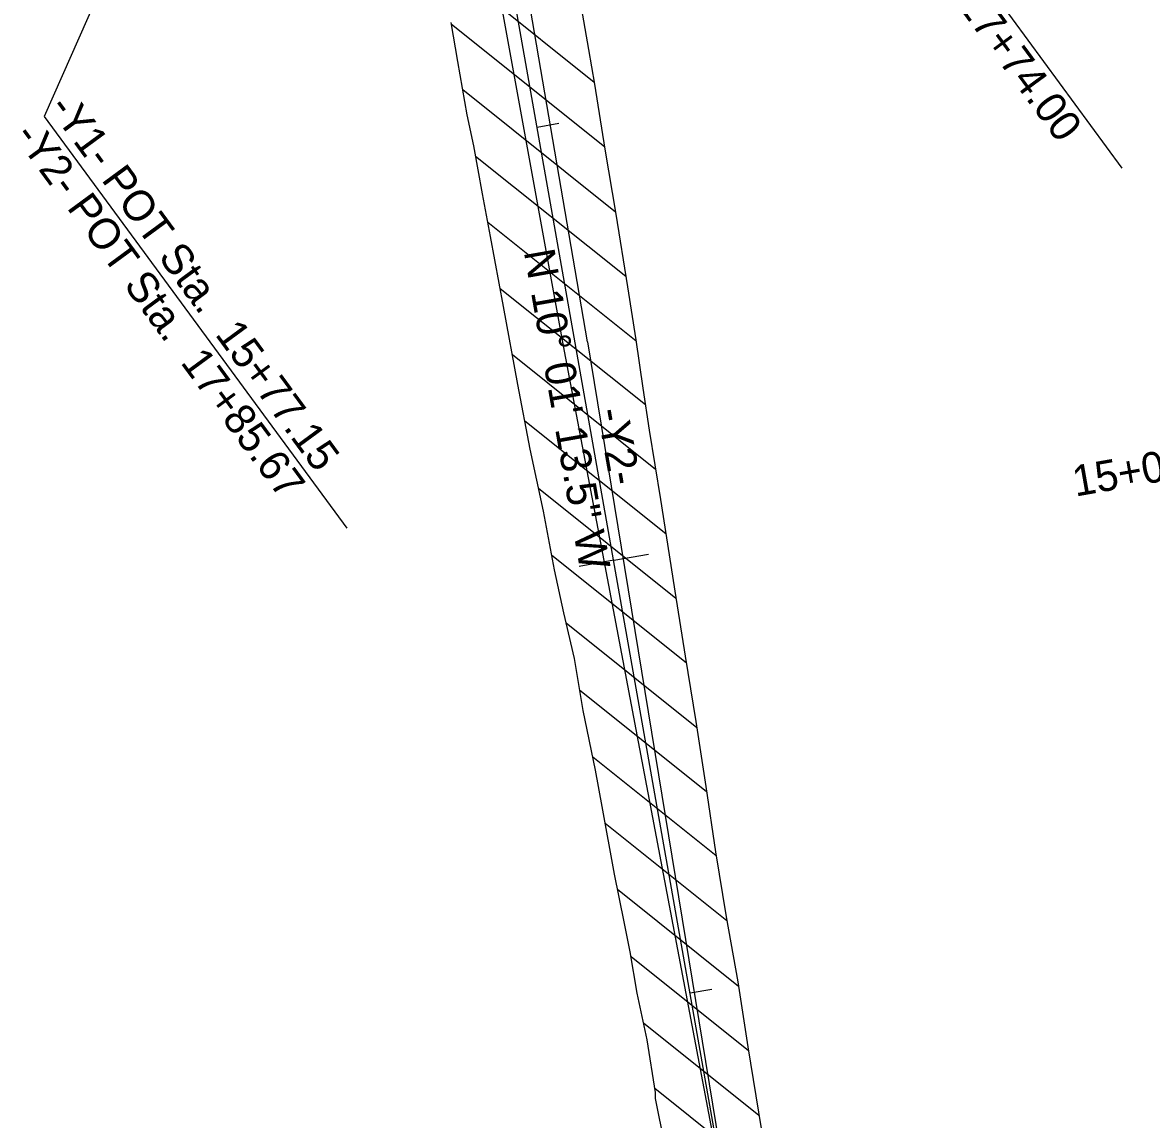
# Model space of a CAD drawing. Extents: x 1762196 to 1766326, y 709922 to 713142.
# Drawn here: x 1763778.9 to 1764035.8, y 712001.2 to 712250.7 of the extents above; entities that cross this region are included whole.
import ezdxf

# ---------------------------------------------------------------- set-up
doc = ezdxf.new("R2010")
doc.units = 0
for name, color, linetype in [('Old_Level_40', 7, 'Continuous'), ('Prop Horizontal Alignment', 7, 'Continuous'), ('Prop Horizontal Alignment Direction Label', 7, 'Continuous'), ('Prop Horizontal Alignment Station Label', 7, 'Continuous'), ('Prop Horizontal Alignment Tick Label', 7, 'Continuous'), ('Prop Horizontal Alignment Tick Large', 7, 'Continuous'), ('Prop Horizontal Alignment Tick Small', 7, 'Continuous'), ('Prop Lane Lines', 7, 'Continuous')]:
    doc.layers.add(name, color=color, linetype=linetype)

msp = doc.modelspace()

# ---------------------------------------------------------------- linework, layer by layer
at = {"layer": 'Old_Level_40'}
for p, q in [((1763873.32, 712265.77), (1763908.97, 712237.21)), ((1763876.51, 712250.39), (1763911.28, 712222.56)), ((1763879.05, 712235.55), (1763913.83, 712207.7)), ((1763881.98, 712220.39), (1763916.14, 712193.04)), ((1763884.77, 712205.35), (1763918.5, 712178.34)), ((1763887.57, 712190.29), (1763920.61, 712163.84)), ((1763890.36, 712175.25), (1763922.92, 712149.18)), ((1763893.17, 712160.19), (1763925.25, 712134.5)), ((1763896.3, 712144.87), (1763927.56, 712119.84)), ((1763899.34, 712129.63), (1763929.89, 712105.16)), ((1763902.6, 712114.2), (1763932.3, 712090.42)), ((1763905.65, 712098.95), (1763934.54, 712075.82)), ((1763908.63, 712083.75), (1763936.73, 712061.25)), ((1763911.47, 712068.67), (1763939.12, 712046.53)), ((1763914.29, 712053.6), (1763941.79, 712031.58)), ((1763917.36, 712038.33), (1763944.08, 712016.94)), ((1763920.19, 712023.25), (1763946.46, 712002.22)), ((1763943.94, 712017.75), (1763953.64, 711957.83)), ((1763922.76, 712008.38), (1763948.84, 711987.5)), ((1763933.12, 711954.2), (1763922.95, 712006.03))]:
    msp.add_line(p, q, dxfattribs=at)
for points in [[(1763889.06, 712351.06), (1763889.2, 712350.17), (1763891.58, 712335.89), (1763894.16, 712321.04), (1763896.99, 712306.32), (1763899.39, 712291.51), (1763902, 712276.76), (1763904.54, 712261.98), (1763905.99, 712254.16), (1763907.71, 712244.63)], [(1763922.95, 712006.03), (1763922.92, 712007.35), (1763921.05, 712019.33), (1763918.73, 712029.93), (1763917.19, 712039.39), (1763915.76, 712046.18), (1763913.6, 712057.05), (1763910.79, 712072.4), (1763909.28, 712080.67), (1763906.43, 712094.25), (1763904.46, 712106.07), (1763902.08, 712116.51), (1763899.97, 712126.28), (1763897.44, 712139.59), (1763894.39, 712153.71), (1763891.62, 712168.43), (1763888.34, 712186.16), (1763885.38, 712202.09), (1763883.55, 712211.79), (1763881.56, 712222.74), (1763880.08, 712229.74), (1763877.93, 712241.89), (1763876.45, 712250.78)], [(1763907.71, 712244.63), (1763909.05, 712236.75), (1763911.37, 712221.97), (1763913.91, 712207.19), (1763916.52, 712190.64)], [(1763916.52, 712190.64), (1763918.47, 712178.59), (1763920.04, 712167.57), (1763921.49, 712158.06), (1763924.02, 712142.29), (1763926.41, 712127.21)], [(1763926.41, 712127.21), (1763927.31, 712121.41), (1763929.65, 712106.6), (1763932.09, 712091.79), (1763934.37, 712076.97), (1763936.59, 712062.14), (1763938.97, 712047.35), (1763941.63, 712032.57), (1763943.94, 712017.75)]]:
    msp.add_lwpolyline(points, dxfattribs=at)
at = {"layer": 'Prop Horizontal Alignment'}
msp.add_line((1763966.92, 711825.6), (1763863.71, 712409.75), dxfattribs=at)
at = {"layer": 'Prop Horizontal Alignment Station Label'}
for p, q in [((1763863.71, 712409.75), (1763783.81, 712229.41)), ((1763959.83, 712311.81), (1764029.03, 712217.65)), ((1763783.81, 712229.41), (1763852.68, 712135.7))]:
    msp.add_line(p, q, dxfattribs=at)
at = {"layer": 'Prop Horizontal Alignment Tick Large'}
for q in [(1763921.29, 712129.83), (1763905.54, 712127.04)]:
    msp.add_line((1763913.41, 712128.43), q, dxfattribs=at)
at = {"layer": 'Prop Horizontal Alignment Tick Small'}
for p, q in [((1763900.94, 712227.78), (1763896.01, 712226.91)), ((1763935.74, 712030.83), (1763930.81, 712029.96))]:
    msp.add_line(p, q, dxfattribs=at)
at = {"layer": 'Prop Lane Lines'}
for p, q in [((1763902.01, 712177.19), (1763874.85, 712326.52)), ((1763907.42, 712178.15), (1763882.06, 712325.99)), ((1763943.86, 711956.1), (1763902.01, 712177.19)), ((1763907.42, 712178.15), (1763943.86, 711956.1))]:
    msp.add_line(p, q, dxfattribs=at)

# ---------------------------------------------------------------- texts
at = {"layer": 'Prop Horizontal Alignment Direction Label'}
for s, rotation, p in [('N 10%%d 01\' 13.5" W', 280.0204, (1763892.94, 712198.63)), ('-Y2-', 280.0243, (1763909.61, 712162.54))]:
    msp.add_text(s, height=7, rotation=rotation, dxfattribs=at).set_placement(p)
at = {"layer": 'Prop Horizontal Alignment Station Label'}
for s, p in [('-Y2- POT Sta.  17+74.00', (1763953.58, 712306.29)), ('-Y1- POT Sta.  15+77.15', (1763784.66, 712231.34)), ('-Y2- POT Sta.  17+85.67', (1763776.8, 712224.97))]:
    msp.add_text(s, height=7, rotation=306.3131, dxfattribs=at).set_placement(p)
at = {"layer": 'Prop Horizontal Alignment Tick Label'}
msp.add_text('15+00', height=7, rotation=10.0204, dxfattribs=at).set_placement((1764018.47, 712142.9))

doc.saveas('drawing.dxf')
